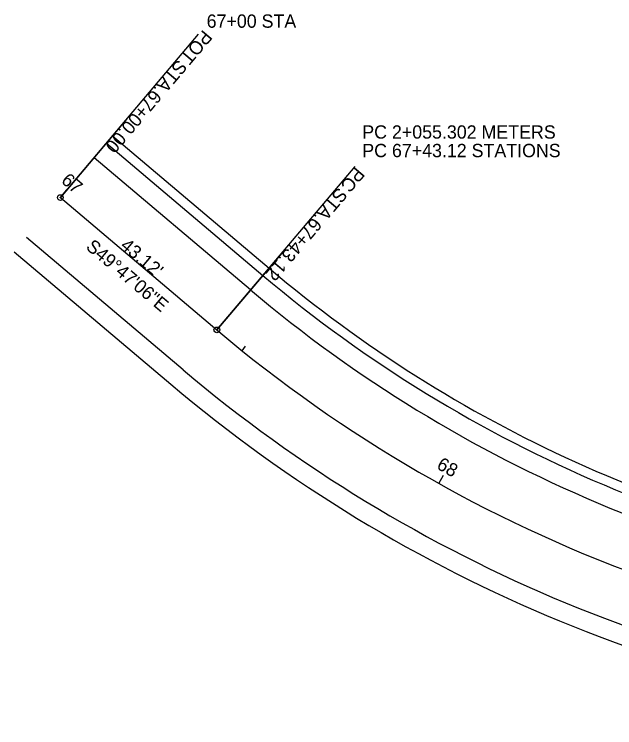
# Model space of a CAD drawing. Extents: x 27625 to 127752, y 6088 to 302357.
# Drawn here: x 27624.5 to 27750.8, y 6092.7 to 6242.9 of the extents above; entities that cross this region are included whole.
import ezdxf

# ---------------------------------------------------------------- set-up
doc = ezdxf.new("R2010")
doc.units = 0
for name, color, linetype in [('DR_X_Cells', 7, 'Continuous'), ('RS_Raster1', 7, 'Continuous'), ('SC_Scratch1', 7, 'Continuous'), ('SC_Scratch2', 7, 'Continuous'), ('SC_Scratch4', 7, 'Continuous'), ('SV_P_Control_Cells_Set', 7, 'Continuous'), ('SV_X_Mon_Cells_Found', 7, 'Continuous'), ('SV_X_Random_Point', 7, 'Continuous'), ('SV_X_Shot_Marker', 7, 'Continuous'), ('UT_X_Telecom_Cells', 7, 'Continuous')]:
    doc.layers.add(name, color=color, linetype=linetype)

msp = doc.modelspace()

# ---------------------------------------------------------------- linework, layer by layer
at = {"layer": 'DR_X_Cells'}
for p, q in [((27634.21, 6204.29), (27635.5, 6205.82)), ((27672.44, 6172.07), (27673.19, 6173.01)), ((27713.83, 6144.13), (27714.8, 6145.87))]:
    msp.add_line(p, q, dxfattribs=at)
at = {"layer": 'RS_Raster1'}
for centre in [(27634.21, 6204.29), (27634.21, 6204.29), (27634.21, 6204.29), (27667.13, 6176.45), (27667.13, 6176.45), (27713.83, 6144.13)]:
    msp.add_circle(centre, 0.05, dxfattribs=at)
at = {"layer": 'SV_P_Control_Cells_Set'}
for p in [(27645.18, 6217.28), (27678.11, 6189.43)]:
    msp.add_line(p, (27678.11, 6189.43), dxfattribs=at)
msp.add_arc((27857.77, 6401.92), 278.26, 229.7841, 261.2786, dxfattribs=at)
at = {"layer": 'SV_X_Mon_Cells_Found'}
for p, q in [((27634.21, 6204.29), (27663.26, 6238.66)), ((27667.13, 6176.45), (27696.19, 6210.82))]:
    msp.add_line(p, q, dxfattribs=at)
for centre in [(27634.21, 6204.29), (27667.13, 6176.45)]:
    msp.add_circle(centre, 0.6, dxfattribs=at)
at = {"layer": 'SV_X_Random_Point'}
for p, q in [((27643.89, 6215.75), (27676.82, 6187.91)), ((27624.52, 6192.84), (27657.45, 6165))]:
    msp.add_line(p, q, dxfattribs=at)
for radius, end in [(280.28, 264.3512), (310.28, 265.2918)]:
    msp.add_arc((27857.78, 6401.93), radius, 229.785, end, dxfattribs=at)
at = {"layer": 'SV_X_Shot_Marker'}
for p, q in [((27648.23, 6220.88), (27634.21, 6204.29)), ((27634.21, 6204.29), (27667.13, 6176.45)), ((27681.16, 6193.04), (27667.13, 6176.45))]:
    msp.add_line(p, q, dxfattribs=at)
msp.add_arc((27857.78, 6401.93), 295.28, 229.785, 270, dxfattribs=at)
msp.add_arc((27857.78, 6401.93), 295.28, 229.785, 270, dxfattribs=at)
at = {"layer": 'UT_X_Telecom_Cells'}
for p, q in [((27674.24, 6184.85), (27641.31, 6212.69)), ((27660.03, 6168.05), (27627.1, 6195.89))]:
    msp.add_line(p, q, dxfattribs=at)
for radius, end in [(284.28, 264.4883), (306.28, 265.1772)]:
    msp.add_arc((27857.78, 6401.93), radius, 229.785, end, dxfattribs=at)

# ---------------------------------------------------------------- texts
at = {"layer": 'DR_X_Cells'}
for s, rotation, p in [('67', 319.785, (27634.2, 6207.58)), ('68', 330.8221, (27713.18, 6147.35))]:
    msp.add_text(s, height=2.8, rotation=rotation, dxfattribs=at).set_placement(p)
at = {"layer": 'SC_Scratch1'}
msp.add_text('S49°47\'06"E', height=2.8, rotation=319.785, dxfattribs=at).set_placement((27639.39, 6193.62))
at = {"layer": 'SC_Scratch2'}
for s, p in [('67+00 STA', (27664.99, 6240.04)), ('PC 2+055.302 METERS', (27697.72, 6216.7)), ('PC 67+43.12 STATIONS', (27697.72, 6212.8))]:
    msp.add_text(s, height=2.8, dxfattribs=at).set_placement(p)
at = {"layer": 'SC_Scratch4'}
msp.add_text("43.12'", height=2.8, rotation=319.785, dxfattribs=at).set_placement((27646.63, 6193.84))
at = {"layer": 'SV_X_Mon_Cells_Found'}
for s, p in [('POT', (27664.25, 6239.77)), (' STA. ', (27659.64, 6234.32)), ('67+00.00', (27653.62, 6227.2)), ('PC', (27696.32, 6210.92)), (' STA. ', (27693.35, 6207.4)), ('67+43.12', (27687.33, 6200.28))]:
    msp.add_text(s, height=2.8, rotation=229.785, dxfattribs=at).set_placement(p)

doc.saveas('drawing.dxf')
